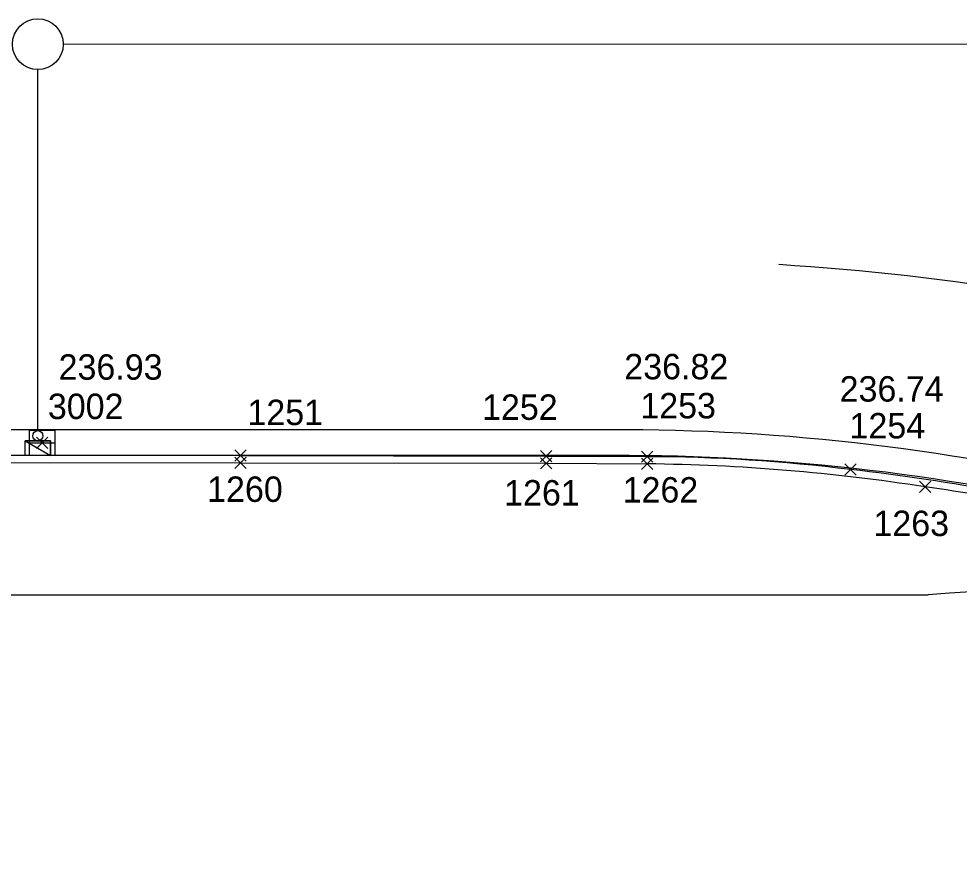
# Model space of a CAD drawing. Extents: x -264205 to -263615, y -1242401 to -1242031.
# Drawn here: x -263854.29 to -263835.79, y -1242320.02 to -1242303.65 of the extents above; entities that cross this region are included whole.
import ezdxf

# ---------------------------------------------------------------- set-up
doc = ezdxf.new("R2010")
doc.units = 0
for name, color, linetype in [('BODY_SYMBOL A CISLO_2-1', 7, 'Continuous'), ('BODY_VYSKA_2-1', 7, 'Continuous'), ('KOORDINACNA_SITUACIA_DSP', 7, 'Continuous'), ('PROJEKT_DRS_TDZ_VODOROVNE', 7, 'Continuous'), ('SO_20-1_OBRUBNIKY_DOLNA_HRANA', 7, 'Continuous'), ('SO_20-1_OBRUBNIKY_HORNA_HRANA', 7, 'Continuous'), ('SO_20-1_UV', 7, 'Continuous')]:
    doc.layers.add(name, color=color, linetype=linetype)

msp = doc.modelspace()

# ---------------------------------------------------------------- linework, layer by layer
at = {"layer": 'BODY_SYMBOL A CISLO_2-1'}
for p, q in [((-263853.942, -1242312.102), (-263853.72, -1242311.88)), ((-263853.72, -1242312.102), (-263853.942, -1242311.88)), ((-263850.04, -1242312.35), (-263849.818, -1242312.129)), ((-263849.818, -1242312.35), (-263850.04, -1242312.129)), ((-263850.039, -1242312.491), (-263849.818, -1242312.269)), ((-263849.818, -1242312.491), (-263850.039, -1242312.269)), ((-263844.027, -1242312.362), (-263843.806, -1242312.14)), ((-263843.806, -1242312.362), (-263844.027, -1242312.14)), ((-263842.042, -1242312.372), (-263841.821, -1242312.15)), ((-263841.821, -1242312.372), (-263842.042, -1242312.15)), ((-263844.027, -1242312.502), (-263843.806, -1242312.282)), ((-263843.806, -1242312.502), (-263844.027, -1242312.282)), ((-263842.041, -1242312.514), (-263841.82, -1242312.292)), ((-263841.82, -1242312.514), (-263842.041, -1242312.292)), ((-263838.041, -1242312.626), (-263837.819, -1242312.404)), ((-263837.819, -1242312.626), (-263838.041, -1242312.404)), ((-263836.573, -1242312.965), (-263836.352, -1242312.745)), ((-263836.352, -1242312.965), (-263836.573, -1242312.745))]:
    msp.add_line(p, q, dxfattribs=at)
at = {"layer": 'KOORDINACNA_SITUACIA_DSP'}
for p, q in [((-263809.091, -1242304.153), (-263853.415, -1242304.148)), ((-263853.915, -1242311.749), (-263853.915, -1242304.647)), ((-263854.165, -1242311.949), (-263853.665, -1242311.949)), ((-263854.165, -1242312.239), (-263854.165, -1242311.949)), ((-263854.165, -1242311.949), (-263853.665, -1242312.239)), ((-263854.165, -1242311.949), (-263853.665, -1242312.239)), ((-263853.665, -1242311.949), (-263854.165, -1242311.949)), ((-263853.665, -1242311.949), (-263853.665, -1242312.239)), ((-263853.665, -1242312.239), (-263853.665, -1242311.949)), ((-263842.601, -1242312.24), (-263924.192, -1242312.232)), ((-263853.665, -1242312.239), (-263854.165, -1242312.239)), ((-264038.443, -1242314.982), (-263836.403, -1242314.982))]:
    msp.add_line(p, q, dxfattribs=at)
for centre, radius in [((-263853.915, -1242304.147), 0.5), ((-263853.915, -1242311.849), 0.1)]:
    msp.add_circle(centre, radius, dxfattribs=at)
for centre, radius, start, end in [((-263842.427, -1242353.351), 41.111, 76.1362, 90.2415), ((-263835.045, -1242327.715), 12.805, 36.9205, 96.0874)]:
    msp.add_arc(centre, radius, start, end, dxfattribs=at)
at = {"layer": 'PROJEKT_DRS_TDZ_VODOROVNE'}
msp.add_line((-263842.661, -1242311.732), (-263980.94, -1242311.732), dxfattribs=at)
for centre, radius, start, end in [((-263842.518, -1242358.966), 50.583, 63.4329, 86.4022), ((-263842.485, -1242353.555), 41.823, 76.1362, 90.2415)]:
    msp.add_arc(centre, radius, start, end, dxfattribs=at)
at = {"layer": 'SO_20-1_OBRUBNIKY_DOLNA_HRANA'}
msp.add_lwpolyline([(-263855.93, -1242312.232), (-263849.929, -1242312.239), (-263843.916, -1242312.251), (-263841.932, -1242312.261)], dxfattribs=at)
for centre, major_axis, ratio, start_param, end_param in [((-263842.029, -1242344.44), (-32.124, -3.857), 0.994471, 4.466507, 4.590549), ((-263842.443, -1242352.313), (-40.262, 2.734), 0.992518, 4.518911, 4.667632)]:
    msp.add_ellipse(centre, major_axis=major_axis, ratio=ratio, start_param=start_param, end_param=end_param, dxfattribs=at)
at = {"layer": 'SO_20-1_OBRUBNIKY_HORNA_HRANA'}
msp.add_lwpolyline([(-263855.926, -1242312.378), (-263849.928, -1242312.38), (-263843.916, -1242312.392), (-263841.931, -1242312.403)], dxfattribs=at)
for centre, major_axis, ratio, start_param, end_param in [((-263842.277, -1242350.519), (-36.177, 12.321), 0.997094, 4.886995, 5.030708), ((-263841.309, -1242347.152), (-34.744, 1.786), 0.995607, 4.494833, 4.62376)]:
    msp.add_ellipse(centre, major_axis=major_axis, ratio=ratio, start_param=start_param, end_param=end_param, dxfattribs=at)
at = {"layer": 'SO_20-1_UV'}
msp.add_line((-263853.831, -1242311.991), (-263853.831, -1242311.991), dxfattribs=at)
msp.add_lwpolyline([(-263854.081, -1242311.991), (-263854.081, -1242311.741), (-263853.581, -1242311.741), (-263853.581, -1242312.241), (-263854.081, -1242312.241), (-263854.081, -1242311.991), (-263853.581, -1242311.991)], dxfattribs=at)

# ---------------------------------------------------------------- texts
at = {"layer": 'BODY_SYMBOL A CISLO_2-1'}
for s, p in [('3002', (-263853.718, -1242311.521)), ('1251', (-263849.793, -1242311.64)), ('1252', (-263845.179, -1242311.537)), ('1253', (-263842.066, -1242311.508)), ('1254', (-263837.951, -1242311.903)), ('1260', (-263850.586, -1242313.151)), ('1261', (-263844.744, -1242313.222)), ('1262', (-263842.414, -1242313.164)), ('1263', (-263837.481, -1242313.823))]:
    msp.add_text(s, height=0.5, dxfattribs=at).set_placement(p)
at = {"layer": 'BODY_VYSKA_2-1'}
for s, p in [('236.93', (-263853.507, -1242310.747)), ('236.82', (-263842.381, -1242310.739)), ('236.74', (-263838.146, -1242311.178))]:
    msp.add_text(s, height=0.5, dxfattribs=at).set_placement(p)

doc.saveas('drawing.dxf')
